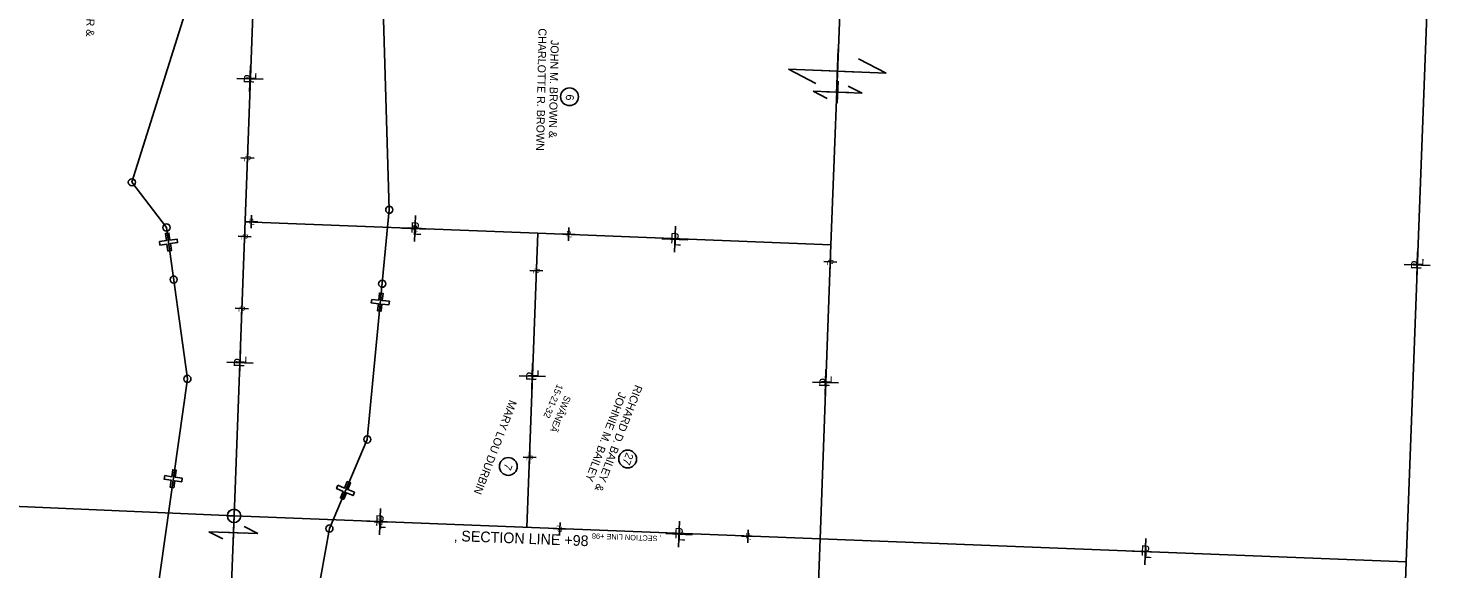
# Model space of a CAD drawing. Extents: x 2814293 to 2835768, y 121185 to 156337.
# Drawn here: x 2823143 to 2826341, y 138763 to 139978 of the extents above; entities that cross this region are included whole.
import ezdxf

# ---------------------------------------------------------------- set-up
doc = ezdxf.new("R2010")
doc.units = 0
for name, color, linetype in [('Photo-Retaining wall', 7, 'Continuous'), ('Roadway-Ditches', 7, 'Continuous'), ('Roadway-Edge of pavement', 7, 'Continuous'), ('Roadway-Edge of shoulder', 7, 'Continuous'), ('Roadway-Entrances', 7, 'Continuous'), ('Roadway-New rw', 7, 'Continuous'), ('Roadway-Safety', 7, 'Continuous'), ('Roadway-Walls', 7, 'Continuous'), ('Scratch-2', 7, 'Continuous'), ('Scratch-4', 7, 'Continuous'), ('Scratch-5', 7, 'Continuous'), ('Text-New rw label', 7, 'Continuous'), ('Traffic_Control-Traffic barriers', 7, 'Continuous')]:
    doc.layers.add(name, color=color, linetype=linetype)

msp = doc.modelspace()

# ---------------------------------------------------------------- linework, layer by layer
at = {"layer": 'Roadway-Ditches'}
for centre in [(2824359.8, 139824.4), (2824490.6, 139009.7), (2824222.1, 138992.9)]:
    msp.add_circle(centre, 20, dxfattribs=at)
at = {"layer": 'Roadway-Edge of pavement'}
for p, q in [((2825017.9, 139832.4), (2824908, 139836.7)), ((2824939.1, 139820.7), (2824908, 139836.7)), ((2824938, 139835.5), (2824987.9, 139833.6)), ((2824963.9, 139859.6), (2824962, 139809.6)), ((2824962.9, 139834.6), (2824962.9, 139834.6)), ((2824986.8, 139848.5), (2825017.9, 139832.4)), ((2823604.9, 138869), (2823603, 138819.1)), ((2823658.9, 138841.9), (2823549, 138846.2)), ((2823580.1, 138830.2), (2823549, 138846.2)), ((2823579, 138845), (2823628.9, 138843.1)), ((2823604, 138844.1), (2823604, 138844.1)), ((2823627.8, 138857.9), (2823658.9, 138841.9))]:
    msp.add_line(p, q, dxfattribs=at)
at = {"layer": 'Roadway-Edge of shoulder'}
for p, q in [((2823640.1, 139835.3), (2823642.2, 139894.1)), ((2823611.7, 139865.7), (2823670.6, 139863.7)), ((2824013.6, 139557.4), (2824011.3, 139498.5)), ((2823983, 139529.1), (2824041.8, 139526.8)), ((2824597.8, 139533.5), (2824595.6, 139474.6)), ((2824567.3, 139505.2), (2824626.1, 139502.9)), ((2826236.7, 139447.3), (2826295.5, 139445.2)), ((2826265, 139416.8), (2826267.1, 139475.7)), ((2823617.5, 139197), (2823620.2, 139255.9)), ((2823589.4, 139227.8), (2823648.3, 139225.1)), ((2824275.2, 139166.3), (2824276.9, 139225.2)), ((2824246.6, 139196.6), (2824305.5, 139195)), ((2824934.6, 139152.4), (2824936.2, 139211.3)), ((2824906, 139182.7), (2824964.9, 139181)), ((2823903.8, 138870), (2823962.7, 138867.8)), ((2823934.4, 138898.3), (2823932.2, 138839.5)), ((2824607, 138870.1), (2824604.7, 138811.2)), ((2824576.4, 138841.8), (2824635.3, 138839.5)), ((2825655.9, 138830.8), (2825653.8, 138771.9)), ((2825625.4, 138802.4), (2825684.3, 138800.3))]:
    msp.add_line(p, q, dxfattribs=at)
at = {"layer": 'Roadway-Entrances'}
for p, q in [((2823605.3, 138881.7), (2823703.8, 141527.1)), ((2826341.2, 141424.5), (2826241.2, 138778.7)), ((2824973.2, 140152.7), (2824947.8, 139491)), ((2824947.8, 139491), (2824923.2, 138830.2)), ((2823605.3, 138881.7), (2820945.5, 138997.4)), ((2823507.8, 136237.3), (2823605.3, 138881.7)), ((2826241.2, 138778.7), (2823605.3, 138881.7)), ((2824923.2, 138830.2), (2824826.9, 136178.8)), ((2826241.2, 138778.7), (2826146.1, 136120.3))]:
    msp.add_line(p, q, dxfattribs=at)
at = {"layer": 'Roadway-New rw'}
for p, q in [((2823954.4, 139570.2), (2823924.4, 140571)), ((2823578.5, 140277.9), (2823375.5, 139631.9)), ((2823375.5, 139631.9), (2823453.4, 139530.3)), ((2823905, 139053.6), (2823954.4, 139570.2)), ((2823453.4, 139530.3), (2823500.4, 139189.9)), ((2823500.4, 139189.9), (2823386.8, 138384.2)), ((2823819.8, 138853.3), (2823905, 139053.6)), ((2823727.7, 138341.1), (2823819.8, 138853.3))]:
    msp.add_line(p, q, dxfattribs=at)
for points in [[(2823437.4, 139498.7), (2823438.6, 139490.8), (2823454.4, 139493), (2823456.6, 139477.2), (2823464.5, 139478.3), (2823462.3, 139494.2), (2823478.2, 139496.4), (2823477.1, 139504.3), (2823461.2, 139502.1), (2823459, 139517.9), (2823451.1, 139516.8), (2823453.3, 139501), (2823437.4, 139498.7)], [(2823914.9, 139368.6), (2823914, 139360.6), (2823930, 139358.9), (2823928.3, 139343), (2823936.3, 139342.2), (2823937.9, 139358.1), (2823953.8, 139356.5), (2823954.7, 139364.4), (2823938.7, 139366.1), (2823940.4, 139382), (2823932.4, 139382.8), (2823930.8, 139366.9), (2823914.9, 139368.6)], [(2823449.4, 138972.2), (2823448.2, 138964.2), (2823464, 138961.9), (2823461.7, 138946.1), (2823469.6, 138944.9), (2823472, 138960.7), (2823487.8, 138958.4), (2823489, 138966.3), (2823473.1, 138968.6), (2823475.5, 138984.4), (2823467.6, 138985.6), (2823465.2, 138969.8), (2823449.4, 138972.2)], [(2823839.1, 138950.5), (2823836, 138943.1), (2823850.7, 138936.9), (2823844.5, 138922.1), (2823851.9, 138919), (2823858.1, 138933.8), (2823872.9, 138927.5), (2823876, 138934.9), (2823861.2, 138941.1), (2823867.5, 138955.9), (2823860.1, 138959), (2823853.9, 138944.2), (2823839.1, 138950.5)]]:
    msp.add_lwpolyline(points, close=True, dxfattribs=at)
at = {"layer": 'Roadway-Walls'}
for p, q in [((2823636.1, 139701.1), (2823635, 139671.7)), ((2823650.3, 139685.9), (2823620.8, 139686.9)), ((2823629.4, 139543.9), (2823658.8, 139542.8)), ((2823644.7, 139558.1), (2823643.5, 139528.6)), ((2824012.6, 139543.4), (2824011.5, 139513.9)), ((2823644, 139509.6), (2823614.6, 139510.7)), ((2823629.8, 139524.9), (2823628.8, 139495.4)), ((2823997.3, 139529.2), (2824026.8, 139528.1)), ((2824343.1, 139516), (2824372.6, 139514.9)), ((2824358.4, 139530.1), (2824357.3, 139500.7)), ((2824285.8, 139448.1), (2824284.9, 139418.6)), ((2824960.9, 139452.7), (2824931.4, 139453.5)), ((2824946.6, 139467.8), (2824945.7, 139438.4)), ((2824300.1, 139432.9), (2824270.6, 139433.8)), ((2823637.6, 139347.4), (2823608.2, 139348.8)), ((2823623.6, 139362.8), (2823622.2, 139333.4)), ((2824270.4, 139028.1), (2824270.1, 138998.7)), ((2824285, 139013.2), (2824255.5, 139013.6)), ((2823949.7, 138867.4), (2823920.2, 138868.5)), ((2823934.4, 138853.2), (2823935.5, 138882.7)), ((2824352.7, 138851.9), (2824323.3, 138853.1)), ((2824337.4, 138837.8), (2824338.6, 138867.2)), ((2824746.6, 138836.4), (2824776, 138835.2)), ((2824761.9, 138850.5), (2824760.7, 138821.1))]:
    msp.add_line(p, q, dxfattribs=at)
at = {"layer": 'Scratch-2'}
for p, q in [((2824963.7, 139931.8), (2824959.9, 139831.8)), ((2825009.5, 139909.6), (2825071.7, 139877.6)), ((2825071.7, 139877.6), (2824851.9, 139886.1)), ((2824914.1, 139854.1), (2824851.9, 139886.1)), ((2824911.8, 139883.8), (2825011.8, 139879.9)), ((2824961.8, 139881.8), (2824961.8, 139881.8))]:
    msp.add_line(p, q, dxfattribs=at)
at = {"layer": 'Scratch-4'}
for p, q in [((2823590.3, 138882.2), (2823605.3, 138881.7)), ((2823605.3, 138881.7), (2823604.8, 138866.7)), ((2823605.3, 138881.7), (2823605.8, 138896.7)), ((2823620.2, 138881.2), (2823605.3, 138881.7))]:
    msp.add_line(p, q, dxfattribs=at)
msp.add_circle((2823605.3, 138881.7), 15, dxfattribs=at)
for start, end in [(88.1, 178.1), (268.1, 358.1)]:
    msp.add_arc((2823605.3, 138881.7), 15, start, end, dxfattribs=at)
at = {"layer": 'Text-New rw label'}
for centre in [(2823375.5, 139631.9), (2823954.4, 139570.2), (2823453.4, 139530.3), (2823469.6, 139413.2), (2823938.5, 139403.8), (2823500.4, 139189.9), (2823905, 139053.6), (2823819.8, 138853.3)]:
    msp.add_circle(centre, 8, dxfattribs=at)
at = {"layer": 'Traffic_Control-Traffic barriers'}
for p, q in [((2823629.9, 139542.9), (2824288.4, 139517.6)), ((2824288.4, 139517.6), (2824263.9, 138855.9)), ((2824288.4, 139517.6), (2824947.8, 139491))]:
    msp.add_line(p, q, dxfattribs=at)

# ---------------------------------------------------------------- texts
at = {"layer": 'Photo-Retaining wall'}
for s, p in [('15-21-32', (2824332.2, 139179.4)), ('SWÃNEÃ', (2824349.6, 139153.9))]:
    msp.add_text(s, height=15, rotation=246.849, dxfattribs=at).set_placement(p)
at = {"layer": 'Roadway-Ditches'}
for s, rotation, p in [('DONALD GARDNER &', 268.849, (2823277.7, 140210.2)), ('CHARLOTTE R. BROWN', 268.849, (2824290.1, 139978.4)), ('JOHN M. BROWN &', 268.849, (2824317.6, 139952.2)), ('6', 268.849, (2824351.6, 139829.6)), ('JOHNIE M. BAILEY', 248.849, (2824471.3, 139161.6)), ('RICHARD D. BAILEY &', 248.849, (2824507.6, 139177.9)), ('MARY LOU DURBIN', 248.849, (2824225, 139143.9)), ('7', 248.849, (2824215.4, 139001.4)), ('27', 248.849, (2824487.7, 139025.5))]:
    msp.add_text(s, height=18, rotation=rotation, dxfattribs=at).set_placement(p)
at = {"layer": 'Roadway-Edge of shoulder'}
for s, rotation, p in [('P', 87.9775, (2823650.4, 139853.7)), ('L', 87.9775, (2823655, 139861.5)), ('P', 357.7804, (2824001.4, 139518.8)), ('L', 357.7804, (2824009.2, 139514.1)), ('P', 357.7804, (2824585.7, 139494.8)), ('L', 357.7804, (2824593.5, 139490.2)), ('P', 87.9775, (2826275.3, 139435.2)), ('L', 87.9775, (2826279.9, 139443.1)), ('P', 87.3561, (2823628, 139215.4)), ('L', 87.3561, (2823632.6, 139223.2)), ('P', 88.3561, (2824285.4, 139184.8)), ('L', 88.3561, (2824289.9, 139192.7)), ('P', 88.3561, (2824944.7, 139170.9)), ('L', 88.3561, (2824949.2, 139178.8)), ('P', 357.7804, (2823922.2, 138859.7)), ('L', 357.7804, (2823930.1, 138855.1)), ('P', 357.7804, (2824594.8, 138831.4)), ('L', 357.7804, (2824602.6, 138826.8)), ('P', 357.9775, (2825643.8, 138792.1)), ('L', 357.9775, (2825651.7, 138787.5))]:
    msp.add_text(s, height=23.6, rotation=rotation, dxfattribs=at).set_placement(p)
at = {"layer": 'Roadway-Safety'}
msp.add_text('‚ SECTION LINE +98', height=12, rotation=177.7804, dxfattribs=at).set_placement((2824566.4, 138836.5))
at = {"layer": 'Roadway-Walls'}
for s, rotation, p in [('L', 267.9775, (2823628.7, 139688)), ('P', 267.9775, (2823630.9, 139691.9)), ('P', 357.7804, (2823638.6, 139538.7)), ('L', 357.7804, (2823642.5, 139536.4)), ('L', 267.9775, (2823622.4, 139511.7)), ('P', 267.9775, (2823624.7, 139515.7)), ('P', 357.7804, (2824006.5, 139524)), ('L', 357.7804, (2824010.4, 139521.7)), ('P', 357.7804, (2824352.3, 139510.8)), ('L', 357.7804, (2824356.2, 139508.5)), ('L', 268.3561, (2824939.2, 139454.6)), ('P', 268.3561, (2824941.5, 139458.6)), ('L', 268.3561, (2824278.4, 139434.9)), ('P', 268.3561, (2824280.7, 139438.8)), ('L', 267.3561, (2823616, 139349.8)), ('P', 267.3561, (2823618.3, 139353.7)), ('L', 269.3561, (2824263.3, 139014.8)), ('P', 269.3561, (2824265.5, 139018.8)), ('L', 177.7804, (2823936.6, 138874.9)), ('P', 177.7804, (2823940.5, 138872.6)), ('L', 177.7804, (2824339.6, 138859.4)), ('P', 177.7804, (2824343.5, 138857.1)), ('P', 357.7804, (2824755.8, 138831.2)), ('L', 357.7804, (2824759.7, 138828.9))]:
    msp.add_text(s, height=11.8, rotation=rotation, dxfattribs=at).set_placement(p)
at = {"layer": 'Scratch-5'}
msp.add_text('‚ SECTION LINE +98', height=24, rotation=357.7804, dxfattribs=at).set_placement((2824100, 138825.2))

doc.saveas('drawing.dxf')
